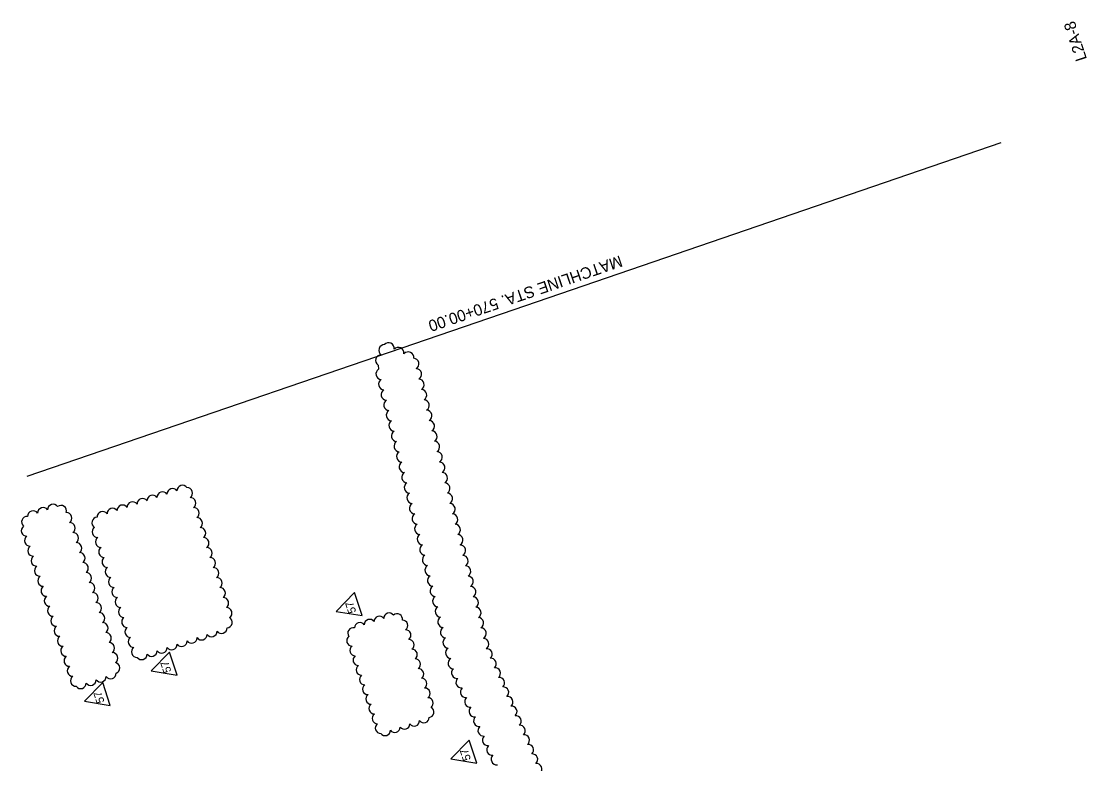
# Model space of a CAD drawing. Extents: x 929207 to 930387, y 631822 to 633132.
# Drawn here: x 929238 to 929984, y 632613 to 633132 of the extents above; entities that cross this region are included whole.
import ezdxf

# ---------------------------------------------------------------- set-up
doc = ezdxf.new("R2010")
doc.units = 0
for name, color, linetype in [('PoleLight', 7, 'Continuous'), ('TextLabel', 7, 'Continuous'), ('TextMinor', 7, 'Continuous')]:
    doc.layers.add(name, color=color, linetype=linetype)

msp = doc.modelspace()

# ---------------------------------------------------------------- linework, layer by layer
at = {"layer": 'PoleLight'}
msp.add_line((929487.8, 632891.98), (929488.23, 632889.16), dxfattribs=at)
for points in [[(929458.53, 632719.84), (929476.63, 632716.9), (929471.36, 632732.95)], [(929329.23, 632678.25), (929347.33, 632675.3), (929342.05, 632691.36)], [(929282.46, 632657), (929300.56, 632654.05), (929295.29, 632670.1)], [(929538.74, 632616.83), (929556.84, 632613.88), (929551.57, 632629.94)]]:
    msp.add_lwpolyline(points, close=True, dxfattribs=at)
for centre, radius, start, end in [((929492.31, 632902.39), 3.94, 90.05322, 235.05322), ((929495.22, 632903.66), 3.95, 352.45125, 137.45125), ((929502.04, 632900.47), 3.95, 352.45125, 137.45125), ((929508.87, 632897.29), 3.95, 352.45125, 137.45125), ((929490.06, 632895.22), 3.94, 90.05322, 235.05322), ((929512.54, 632892.86), 3.92, 301.51367, 86.51367), ((929490.27, 632885.83), 3.9, 121.51367, 266.51367), ((929514.35, 632885.61), 3.92, 301.51367, 86.51367), ((929492.07, 632878.61), 3.9, 121.51367, 266.51367), ((929516.16, 632878.36), 3.92, 301.51367, 86.51367), ((929493.88, 632871.39), 3.9, 121.51367, 266.51367), ((929517.97, 632871.11), 3.92, 301.51367, 86.51367), ((929495.68, 632864.17), 3.9, 121.51367, 266.51367), ((929519.78, 632863.86), 3.92, 301.51367, 86.51367), ((929497.48, 632856.95), 3.9, 121.51367, 266.51367), ((929521.59, 632856.61), 3.92, 301.51367, 86.51367), ((929499.28, 632849.73), 3.9, 121.51367, 266.51367), ((929523.4, 632849.37), 3.92, 301.51367, 86.51367), ((929501.09, 632842.51), 3.9, 121.51367, 266.51367), ((929525.21, 632842.12), 3.92, 301.51367, 86.51367), ((929502.89, 632835.28), 3.9, 121.51367, 266.51367), ((929527.02, 632834.87), 3.92, 301.51367, 86.51367), ((929504.69, 632828.06), 3.9, 121.51367, 266.51367), ((929528.83, 632827.62), 3.92, 301.51367, 86.51367), ((929506.49, 632820.84), 3.9, 121.51367, 266.51367), ((929530.64, 632820.37), 3.92, 301.51367, 86.51367), ((929508.29, 632813.62), 3.9, 121.51367, 266.51367), ((929532.44, 632813.12), 3.92, 301.51367, 86.51367), ((929344.06, 632801.82), 3.86, 35.68663, 180.68663), ((929351.05, 632804.12), 3.86, 35.68663, 180.68663), ((929354.22, 632802.51), 3.86, 305.68663, 90.68663), ((929510.1, 632806.4), 3.9, 121.51367, 266.51367), ((929534.25, 632805.87), 3.92, 301.51367, 86.51367), ((929316.1, 632792.64), 3.86, 35.68663, 180.68663), ((929323.09, 632794.94), 3.86, 35.68663, 180.68663), ((929330.08, 632797.23), 3.86, 35.68663, 180.68663), ((929337.07, 632799.53), 3.86, 35.68663, 180.68663), ((929356.52, 632795.52), 3.86, 305.68663, 90.68663), ((929511.9, 632799.18), 3.9, 121.51367, 266.51367), ((929536.06, 632798.63), 3.92, 301.51367, 86.51367), ((929246.59, 632786.24), 3.86, 35.68663, 180.68663), ((929253.58, 632788.54), 3.86, 35.68663, 180.68663), ((929260.57, 632790.84), 3.86, 35.68663, 180.68663), ((929266.09, 632790.05), 3.86, 343.12086, 128.12086), ((929269.83, 632785.07), 3.86, 305.68663, 90.68663), ((929295.14, 632785.75), 3.86, 35.68663, 180.68663), ((929302.13, 632788.05), 3.86, 35.68663, 180.68663), ((929309.11, 632790.34), 3.86, 35.68663, 180.68663), ((929358.82, 632788.54), 3.86, 305.68663, 90.68663), ((929513.7, 632791.96), 3.9, 121.51367, 266.51367), ((929537.87, 632791.38), 3.92, 301.51367, 86.51367), ((929242.39, 632782.35), 3.86, 85.06215, 230.06215), ((929272.12, 632778.08), 3.86, 305.68663, 90.68663), ((929291.5, 632781.86), 3.86, 93.25498, 238.25498), ((929361.11, 632781.55), 3.86, 305.68663, 90.68663), ((929515.5, 632784.73), 3.9, 121.51367, 266.51367), ((929539.68, 632784.13), 3.92, 301.51367, 86.51367), ((929242.17, 632776.25), 3.86, 125.68663, 270.68663), ((929274.42, 632771.09), 3.86, 305.68663, 90.68663), ((929291.72, 632775.45), 3.86, 125.68663, 270.68663), ((929363.41, 632774.56), 3.86, 305.68663, 90.68663), ((929517.31, 632777.51), 3.9, 121.51367, 266.51367), ((929541.49, 632776.88), 3.92, 301.51367, 86.51367), ((929244.47, 632769.26), 3.86, 125.68663, 270.68663), ((929276.72, 632764.09), 3.86, 305.68663, 90.68663), ((929294.02, 632768.46), 3.86, 125.68663, 270.68663), ((929365.7, 632767.57), 3.86, 305.68663, 90.68663), ((929519.11, 632770.29), 3.9, 121.51367, 266.51367), ((929520.91, 632763.07), 3.9, 121.51367, 266.51367), ((929543.3, 632769.63), 3.92, 301.51367, 86.51367), ((929246.76, 632762.26), 3.86, 125.68663, 270.68663), ((929279.02, 632757.1), 3.86, 305.68663, 90.68663), ((929296.31, 632761.47), 3.86, 125.68663, 270.68663), ((929368, 632760.58), 3.86, 305.68663, 90.68663), ((929522.71, 632755.85), 3.9, 121.51367, 266.51367), ((929545.11, 632762.38), 3.92, 301.51367, 86.51367), ((929546.92, 632755.13), 3.92, 301.51367, 86.51367), ((929249.06, 632755.27), 3.86, 125.68663, 270.68663), ((929281.31, 632750.1), 3.86, 305.68663, 90.68663), ((929298.61, 632754.48), 3.86, 125.68663, 270.68663), ((929370.3, 632753.59), 3.86, 305.68663, 90.68663), ((929524.52, 632748.63), 3.9, 121.51367, 266.51367), ((929548.73, 632747.89), 3.92, 301.51367, 86.51367), ((929251.36, 632748.28), 3.86, 125.68663, 270.68663), ((929253.66, 632741.28), 3.86, 125.68663, 270.68663), ((929283.61, 632743.11), 3.86, 305.68663, 90.68663), ((929300.9, 632747.49), 3.86, 125.68663, 270.68663), ((929372.59, 632746.6), 3.86, 305.68663, 90.68663), ((929526.32, 632741.41), 3.9, 121.51367, 266.51367), ((929550.54, 632740.64), 3.92, 301.51367, 86.51367), ((929255.95, 632734.29), 3.86, 125.68663, 270.68663), ((929285.91, 632736.12), 3.86, 305.68663, 90.68663), ((929303.2, 632740.5), 3.86, 125.68663, 270.68663), ((929305.5, 632733.51), 3.86, 125.68663, 270.68663), ((929374.89, 632739.61), 3.86, 305.68663, 90.68663), ((929528.12, 632734.19), 3.9, 121.51367, 266.51367), ((929552.34, 632733.39), 3.92, 301.51367, 86.51367), ((929258.25, 632727.29), 3.86, 125.68663, 270.68663), ((929288.21, 632729.12), 3.86, 305.68663, 90.68663), ((929307.79, 632726.53), 3.86, 125.68663, 270.68663), ((929377.18, 632732.63), 3.86, 305.68663, 90.68663), ((929379.48, 632725.64), 3.86, 305.68663, 90.68663), ((929529.92, 632726.96), 3.9, 121.51367, 266.51367), ((929554.15, 632726.14), 3.92, 301.51367, 86.51367), ((929260.55, 632720.3), 3.86, 125.68663, 270.68663), ((929290.51, 632722.13), 3.86, 305.68663, 90.68663), ((929310.09, 632719.54), 3.86, 125.68663, 270.68663), ((929381.78, 632718.65), 3.86, 305.68663, 90.68663), ((929531.72, 632719.74), 3.9, 121.51367, 266.51367), ((929555.96, 632718.89), 3.92, 301.51367, 86.51367), ((929262.85, 632713.31), 3.86, 125.68663, 270.68663), ((929292.8, 632715.13), 3.86, 305.68663, 90.68663), ((929312.38, 632712.55), 3.86, 125.68663, 270.68663), ((929382, 632712.24), 3.86, 273.25498, 58.25498), ((929481.98, 632710.55), 3.74, 35.68663, 180.68663), ((929488.76, 632712.78), 3.74, 35.68663, 180.68663), ((929495.54, 632715), 3.74, 35.68663, 180.68663), ((929501.17, 632714.49), 3.74, 348.79709, 133.79709), ((929533.53, 632712.52), 3.9, 121.51367, 266.51367), ((929557.77, 632711.64), 3.92, 301.51367, 86.51367), ((929265.14, 632706.31), 3.86, 125.68663, 270.68663), ((929295.1, 632708.14), 3.86, 305.68663, 90.68663), ((929314.68, 632705.56), 3.86, 125.68663, 270.68663), ((929378.36, 632708.34), 3.86, 215.68663, 0.68663), ((929470.38, 632704.7), 3.74, 73.23706, 218.23706), ((929475.2, 632708.32), 3.74, 35.68663, 180.68663), ((929504.89, 632710.02), 3.74, 305.68663, 90.68663), ((929507.11, 632703.24), 3.74, 305.68663, 90.68663), ((929535.33, 632705.3), 3.9, 121.51367, 266.51367), ((929559.58, 632704.39), 3.92, 301.51367, 86.51367), ((929267.44, 632699.32), 3.86, 125.68663, 270.68663), ((929297.4, 632701.15), 3.86, 305.68663, 90.68663), ((929316.98, 632698.57), 3.86, 125.68663, 270.68663), ((929357.39, 632701.46), 3.86, 215.68663, 0.68663), ((929364.38, 632703.75), 3.86, 215.68663, 0.68663), ((929371.37, 632706.05), 3.86, 215.68663, 0.68663), ((929469.63, 632699.34), 3.74, 125.68663, 270.68663), ((929509.34, 632696.46), 3.74, 305.68663, 90.68663), ((929537.13, 632698.08), 3.9, 121.51367, 266.51367), ((929561.39, 632697.15), 3.92, 301.51367, 86.51367), ((929269.74, 632692.32), 3.86, 125.68663, 270.68663), ((929299.7, 632694.15), 3.86, 305.68663, 90.68663), ((929319.27, 632691.58), 3.86, 125.68663, 270.68663), ((929329.44, 632692.27), 3.86, 215.68663, 0.68663), ((929336.43, 632694.57), 3.86, 215.68663, 0.68663), ((929343.42, 632696.86), 3.86, 215.68663, 0.68663), ((929350.4, 632699.16), 3.86, 215.68663, 0.68663), ((929471.86, 632692.56), 3.74, 125.68663, 270.68663), ((929511.57, 632689.68), 3.74, 305.68663, 90.68663), ((929538.93, 632690.86), 3.9, 121.51367, 266.51367), ((929563.83, 632690), 3.82, 310.92371, 95.92371), ((929272.04, 632685.33), 3.86, 125.68663, 270.68663), ((929301.99, 632687.16), 3.86, 305.68663, 90.68663), ((929322.45, 632689.98), 3.86, 215.68663, 0.68663), ((929474.08, 632685.78), 3.74, 125.68663, 270.68663), ((929513.8, 632682.9), 3.74, 305.68663, 90.68663), ((929540.74, 632683.64), 3.9, 121.51367, 266.51367), ((929566.73, 632683.31), 3.82, 310.92371, 95.92371), ((929274.34, 632678.34), 3.86, 125.68663, 270.68663), ((929303.29, 632680.28), 3.86, 290.69182, 75.69182), ((929476.31, 632679), 3.74, 125.68663, 270.68663), ((929516.02, 632676.12), 3.74, 305.68663, 90.68663), ((929543.1, 632676.87), 3.87, 132.15746, 277.15746), ((929569.63, 632676.62), 3.82, 310.92371, 95.92371), ((929276.63, 632671.34), 3.86, 125.68663, 270.68663), ((929279.81, 632669.73), 3.86, 215.68663, 0.68663), ((929286.81, 632672.03), 3.86, 215.68663, 0.68663), ((929293.8, 632674.33), 3.86, 215.68663, 0.68663), ((929300.8, 632676.63), 3.86, 215.68663, 0.68663), ((929478.54, 632672.22), 3.74, 125.68663, 270.68663), ((929518.25, 632669.34), 3.74, 305.68663, 90.68663), ((929546.18, 632670.16), 3.87, 132.15746, 277.15746), ((929572.53, 632669.93), 3.82, 310.92371, 95.92371), ((929480.77, 632665.44), 3.74, 125.68663, 270.68663), ((929520.48, 632662.56), 3.74, 305.68663, 90.68663), ((929549.26, 632663.44), 3.87, 132.15746, 277.15746), ((929575.43, 632663.24), 3.82, 310.92371, 95.92371), ((929482.99, 632658.66), 3.74, 125.68663, 270.68663), ((929485.22, 632651.88), 3.74, 125.68663, 270.68663), ((929522.71, 632655.78), 3.74, 305.68663, 90.68663), ((929552.34, 632656.73), 3.87, 132.15746, 277.15746), ((929578.33, 632656.55), 3.82, 310.92371, 95.92371), ((929487.45, 632645.1), 3.74, 125.68663, 270.68663), ((929523.15, 632649.43), 3.74, 277.25855, 62.25855), ((929555.43, 632650.02), 3.87, 132.15746, 277.15746), ((929581.22, 632649.86), 3.82, 310.92371, 95.92371), ((929489.67, 632638.32), 3.74, 125.68663, 270.68663), ((929506.32, 632641.22), 3.74, 215.68663, 0.68663), ((929513.1, 632643.45), 3.74, 215.68663, 0.68663), ((929519.88, 632645.67), 3.74, 215.68663, 0.68663), ((929558.51, 632643.3), 3.87, 132.15746, 277.15746), ((929584.12, 632643.17), 3.82, 310.92371, 95.92371), ((929587.02, 632636.48), 3.82, 310.92371, 95.92371), ((929492.76, 632636.76), 3.74, 215.68663, 0.68663), ((929499.54, 632638.99), 3.74, 215.68663, 0.68663), ((929561.59, 632636.59), 3.87, 132.15746, 277.15746), ((929564.67, 632629.88), 3.87, 132.15746, 277.15746), ((929589.92, 632629.78), 3.82, 310.92371, 95.92371), ((929567.75, 632623.16), 3.87, 132.15746, 277.15746), ((929592.82, 632623.09), 3.82, 310.92371, 95.92371), ((929570.83, 632616.45), 3.87, 132.15746, 277.15746), ((929595.72, 632616.4), 3.82, 310.92371, 95.92371), ((929598.62, 632609.71), 3.82, 310.92371, 95.92371)]:
    msp.add_arc(centre, radius, start, end, dxfattribs=at)
at = {"layer": 'TextMinor'}
msp.add_lwpolyline([(929923.44, 633047.35), (929582.85, 632930.75), (929242.25, 632814.15)], dxfattribs=at)

# ---------------------------------------------------------------- texts
at = {"layer": 'PoleLight'}
for p in [(929472.65, 632719.5), (929343.34, 632677.9), (929296.58, 632656.65), (929552.86, 632616.48)]:
    msp.add_text('57', height=5.6, rotation=108.18663, dxfattribs=at).set_placement(p)
at = {"layer": 'TextLabel'}
msp.add_text('L2A-8', height=8, rotation=108.18663, dxfattribs=at).set_placement((929983.78, 633105.98))
at = {"layer": 'TextMinor'}
msp.add_text('MATCHLINE STA. 570+00.00', height=8, rotation=198.89818, dxfattribs=at).set_placement((929657.02, 632968.83))

doc.saveas('drawing.dxf')
